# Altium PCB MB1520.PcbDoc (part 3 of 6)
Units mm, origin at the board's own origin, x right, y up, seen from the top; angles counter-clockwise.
Board outline 159 x 88 mm, 6 copper layers (Top Layer, Signal Layer 1, Signal Layer 2, Signal Layer 3, Signal Layer 4, Bottom Layer), stack 1.572 mm thick; 473 components, 377 nets, 1832 pads, 1378 vias.
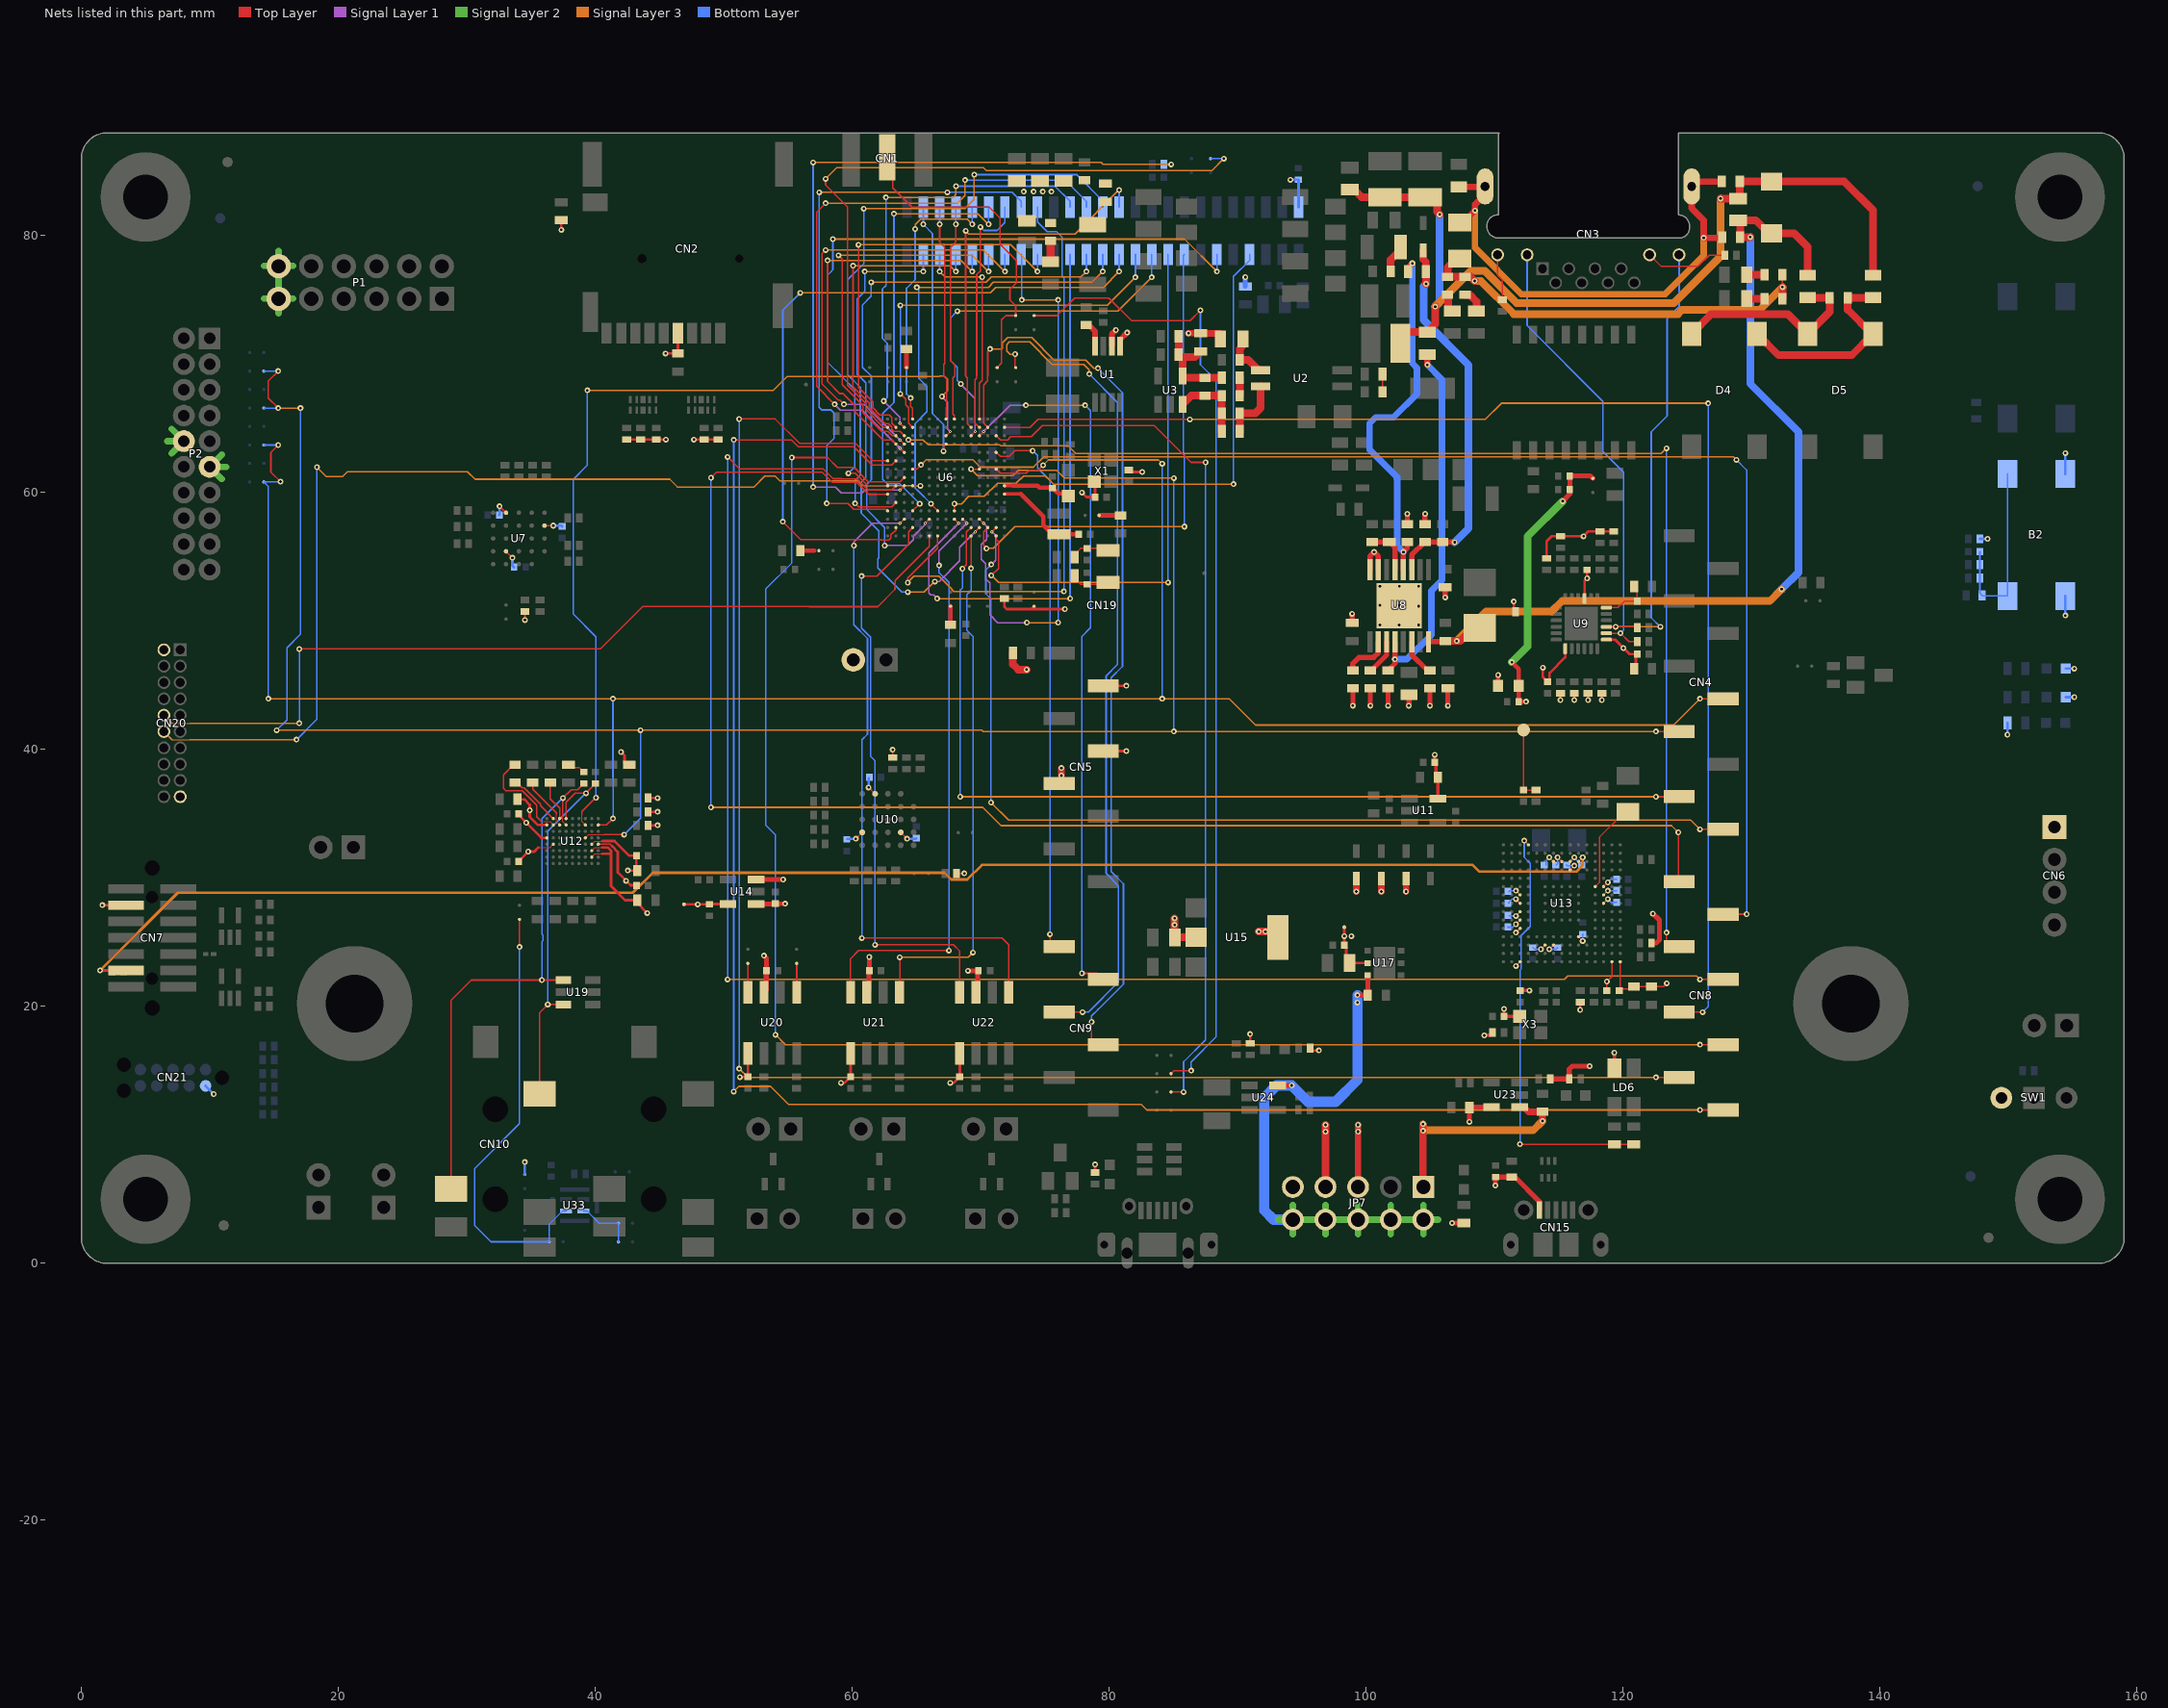
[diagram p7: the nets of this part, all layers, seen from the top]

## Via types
v1: diameter 0.45, hole 0.2, Top Layer to Bottom Layer, tented both sides, 1099 vias
v2: diameter 0.25, hole 0.1, Top Layer to Signal Layer 1, tented both sides, 217 vias
v3: diameter 0.25, hole 0.1, Signal Layer 4 to Bottom Layer, tented both sides, 53 vias
v4: diameter 0.6, hole 0.3, Top Layer to Bottom Layer, tented both sides, 9 vias

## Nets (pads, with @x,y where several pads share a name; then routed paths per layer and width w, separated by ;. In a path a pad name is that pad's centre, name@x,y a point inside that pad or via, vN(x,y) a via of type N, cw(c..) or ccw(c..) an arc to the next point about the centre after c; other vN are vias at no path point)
1V8: C74.2 C82.1 C86.1 C93.2 TP4.1 U12.D1 U12.D8 U12.G9 U14.5 | length 15.6
  Top Layer w0.09: 35.575,32.375 36.475,32.375 U12.D8@36.725,32.625
  Top Layer w0.1: U12.D1@40.225,32.625 41.15,32.625 41.288,32.487
  Top Layer w0.2: C74.2@33.95,36.125 34.475,36.125 34.9,35.7 34.9,34.75 35.525,34.125 U12.G9@36.225,34.125 ; C82.1@34.025,31.3 v1(34.775,32.05) 35.25,32.05 35.575,32.375 ; 41.288,32.487 41.75,32.025 41.75,30.425 42.75,29.425 C86.1@43.2,29.425 ; TP4.1@46.9,27.95 v1(47.975,27.95) C93.2@48.9,27.95 ; C93.2@48.9,27.975 U14.5@50.325,27.975
  other v1: 42.4,29.775 34.9,35.275
3V3: B2.1 B2.2 C24.1 C37.2 C46.1 C77.1 C81.1 C83.2 C87.2 C88.2 C95.1 C96.2 C109.2 C110.2 C111.2 C116.1 C132.2 C136.2 C139.2 C140.2 C141.2 C143.2 CN2.4 CN5.2 CN5.4 CN7.3 CN19.50 CN20.2 CN20.19 CN21.1 JP1.2 L4.2 LD1.1 LD2.1 P1.6 P1.12 R3.2 R27.2 R28.2 R29.2 R30.2 R31.2 R41.2 R49.2 R50.2 R51.1 R55.2 R63.1 R65.2 R67.1 R81.2 R86.1 R90.2 R92.2 R94.1 R102.2 R112.2 R117.2 R118.2 R132.2 R140.2 R145.2 SB22.1 SB36.2 SW1.2 TP5.1 U7.B4 U7.D1 U7.E4 U9.9 U10.B4 U10.D1 U10.E4 U12.B2 U12.C2 U12.D2 U12.E9 U14.1 U14.3 U17.2 U20.5 U21.5 U22.5 X1.4 | length 106.5
  Top Layer w0.09: U12.B2@39.725,31.625 39.975,31.875 40.55,31.875 ; U12.C2@39.725,32.125 39.975,32.375 40.55,32.375 ; U12.D2@39.725,32.625 39.975,32.875 40.55,32.875
  Top Layer w0.127: v1(32.55,58.925) U7.E4@33.05,58.425 ; U7.B4@33.05,55.425 v1(33.55,54.925) ; v1(34.525,50.075) R65.2@34.525,50.75 ; U7.D1@36.05,57.425 v1(36.725,57.425) ; v1(60.275,33.05) U10.E4@60.775,33.55 ; v1(61.275,37.05) U10.D1@61.775,36.55 ; R81.2@63.15,39.375 v1(63.15,39.975) ; U10.B4@63.775,33.55 v1(64.275,33.05) ; R102.2@68.125,30.35 v1(68.725,30.35)
  Top Layer w0.2: v1(1.629,27.879) CN7.3@3.479,27.879 ; C77.1@34.025,34.975 34.025,34.9 35.8,33.125 U12.E9@36.225,33.125 ; v1(37.35,80.45) R3.2@37.35,81.2 ; 40.55,31.875 41.175,31.875 41.225,31.925 ; 40.55,32.375 40.976,32.375 41.225,32.126 41.225,31.925 ; 40.55,32.875 41.5,32.875 42.65,31.725 C81.1@43.2,31.725 43.2,30.65 C83.2@43.275,30.575 v1(42.525,30.575) ; v1(42,39.8) 42.275,39.525 42.275,38.9 42.35,38.825 R86.1@42.65,38.825 ; R27.2@42.45,64.125 R28.2@43.525,64.125 R29.2@44.75,64.125 v1(45.5,64.125) ; v1(44.05,27.275) 43.275,28.05 C88.2@43.275,28.275 42.325,28.275 41.225,29.375 41.225,31.925 ; R94.1@44.1,34.1 v1(44.85,34.1) ; R92.2@44.1,35.15 v1(44.85,35.15) ; R90.2@44.1,36.225 v1(44.85,36.225) ; v1(45.475,70.825) C24.1@46.425,70.825 CN2.4@46.425,72.4 ; v1(47.675,64.125) R30.2@48.475,64.125 R31.2@49.55,64.125 ; v1(51.25,14.5) 51.85,14.5 C109.2@51.87,14.48 ; U20.5@51.87,16.35 51.875,16.345 C109.2@51.875,14.525 ; v1(59.125,14.05) 59.4,14.05 C110.2@59.875,14.525 59.875,16.345 U21.5@59.87,16.35 ; v1(67.625,14.05) 67.9,14.05 C111.2@68.375,14.525 68.375,16.345 U22.5@68.37,16.35 ; R63.1@71.85,51.75 71.85,51.098 72.023,50.925 73.925,50.925 ; SB22.1@74.15,51.15 73.925,50.925 ; v1(76.55,50.925) 73.925,50.925 ; v1(77.875,60) 78.225,59.65 C37.2@78.9,59.65 78.9,60.8 X1.4@78.85,60.85 ; R132.2@78.9,7.075 v1(78.9,7.7) ; CN5.4@79.541,39.88 v1(81.335,39.88) ; CN5.2@79.541,44.96 v1(81.335,44.96) ; R41.2@81.525,61.75 81.675,61.6 v1(82.575,61.6) ; R117.2@90.975,17.125 v1(90.975,17.85) ; R118.2@95.637,16.764 95.826,16.575 v1(96.325,16.575) ; TP5.1@98.325,26.2 TP5.1@98.3,26.175 v1(98.3,25.475) C95.1@98.3,24.775 98.45,24.625 98.45,23.625 C96.2@98.7,23.375 U17.2@100.125,23.375 ; v1(111.498,51.515) 111.498,50.852 R67.1@111.625,50.725 ; R55.2@114.05,54.875 114.05,56.225 114.425,56.6 R51.1@115.125,56.6 v1(116.925,56.6) 117.3,56.975 R49.2@118.2,56.975 R50.2@119.275,56.975 ; v1(116.661,19.731) R112.2@116.661,20.339 ; U9.9@117,51.75 117,53.125 v1(117.2,53.325) C46.1@117.2,53.975
  Top Layer w0.35: U14.1@52.525,27.975 54,27.975 C87.2@54.025,28 v1(54.775,28) ; U14.3@52.525,29.875 v1(54.625,29.875) ; L4.2@110.275,44.95 v1(110.275,45.8)
  Signal Layer 2 w0.5: 14.2,75.11 P1.6@15.35,75.11 ; 14.2,77.65 P1.12@15.35,77.65 ; 15.35,73.96 P1.6@15.35,75.11 ; 15.35,78.8 P1.12@15.35,77.65 ; 16.5,75.11 P1.6@15.35,75.11 ; 16.5,77.65 P1.12@15.35,77.65 ; P1.6@15.35,75.11 P1.12@15.35,77.65
  Bottom Layer w0.127: C143.2@59.575,33 C143.2@59.625,33.05 ; C140.2@61.275,37.775 C140.2@61.325,37.825 ; C141.2@64.95,33.05 C141.2@65,33.1
  Bottom Layer w0.2: CN21.1@9.665,13.815 v1(10.305,13.175) ; C132.2@32.525,58.25 32.55,58.275 v1(32.55,58.925) ; v1(33.55,54.925) 33.55,54.315 C139.2@33.675,54.19 ; SB36.2@34.512,6.919 v1(34.512,7.887) ; v1(36.725,57.425) 37.375,57.425 C136.2@37.425,57.375 ; C143.2@59.625,33.05 v1(60.275,33.05) ; v1(61.275,37.05) C140.2@61.275,37.775 ; v1(64.275,33.05) C141.2@64.95,33.05 ; v1(94.1,84.35) C116.1@94.725,84.35 94.74,84.335 CN19.50@94.74,82.217 ; R140.2@147.775,56.4 v1(148.375,56.4) ; v1(149.925,41.15) R145.2@149.925,42.075 ; v1(154.425,50.425) B2.1@154.425,51.95 ; B2.2@154.425,61.45 v1(154.425,63.075) ; LD1.1@154.45,44.075 v1(155.125,44.075) ; LD2.1@154.45,46.3 v1(155.125,46.3)
  other v1: 98.85,25.475 34.625,34.3
3V3_STLK: C63.2 C70.2 C101.2 C102.2 C103.2 C105.2 C106.2 C108.2 C144.2 C145.2 C146.2 C147.2 C148.2 C149.2 C150.2 C151.2 C152.2 C153.2 C154.2 C155.2 C156.2 C157.2 CN6.1 LD6.4 R115.1 U11.5 U13.C1 U13.C5 U13.C6 U13.C7 U13.C8 U13.C9 U13.F3 U13.G3 U13.G13 U13.H13 U13.J12 U13.J13 U13.K4 U13.N8 U13.N9 U13.N10 U13.P1 U13.R1 X3.4 | length 33.4
  Top Layer w0.12: v1(111.658,23.152) U13.C1@111.983,23.477 ; v1(111.658,25.752) U13.C5@111.983,26.077 ; v1(111.658,26.402) U13.C6@111.983,26.727 ; v1(111.658,27.052) U13.C7@111.983,27.377 ; v1(111.658,28.352) U13.C8@111.983,28.027 ; v1(111.658,29.002) U13.C9@111.983,28.677 ; v1(113.608,24.452) U13.F3@113.933,24.777 ; v1(114.258,24.452) U13.G3@114.583,24.777 ; v1(114.258,31.602) U13.G13@114.583,31.277 ; v1(114.908,31.602) U13.H13@115.233,31.277 ; U13.J12@115.883,30.627 v1(116.208,30.952) ; U13.J13@115.883,31.277 v1(116.208,31.602) ; U13.K4@116.533,25.427 v1(116.858,25.102) ; U13.N8@118.483,28.027 v1(118.808,28.352) ; U13.N9@118.483,28.677 v1(118.808,29.002) ; U13.N10@118.483,29.327 v1(118.808,29.652) ; C105.2@118.736,21.239 v1(118.736,21.936) 119.133,22.333 U13.P1@119.133,23.477 ; C106.2@119.686,21.239 C106.2@119.783,21.336 ; U13.R1@119.783,23.477 C106.2@119.783,21.336 ; v1(123.4,21.8) 123.139,21.539 C102.2@122.211,21.539 C101.2@120.836,21.539 120.647,21.35 119.797,21.35 C106.2@119.783,21.336
  Top Layer w0.254: v1(105.336,39.586) C63.2@105.336,38.989 105.425,38.901 105.425,38.001 C70.2@105.586,37.839 U11.5@105.586,36.189 ; v1(109.2,17.75) 109.622,17.75 R115.1@109.836,17.964 ; v1(110.736,19.811) C108.2@110.736,19.214 X3.4@111.961,19.214 ; C103.2@111.986,21.239 v1(112.711,21.239) ; v1(119.325,16.4) 119.325,15.201 LD6.4@119.336,15.189
  Bottom Layer w0.12: C155.2@111.025,26.175 111.431,26.175 v1(111.658,26.402) ; C152.2@111.111,28.014 111.111,28.111 111.352,28.352 v1(111.658,28.352) ; C150.2@111.111,28.914 111.199,29.002 v1(111.658,29.002) ; C153.2@111.125,27.05 111.127,27.052 v1(111.658,27.052) ; C157.2@112.975,24.575 113.098,24.452 v1(113.608,24.452) ; C147.2@114,31 114,31.344 v1(114.258,31.602) ; v1(114.258,24.452) 114.777,24.452 C156.2@114.9,24.575 ; C146.2@114.8,31 114.908,31.108 v1(114.908,31.602) ; C145.2@115.6,31 115.648,30.952 v1(116.208,30.952) ; v1(116.208,31.602) 116.208,31.592 C144.2@116.8,31 ; v1(116.858,25.102) 116.858,25.608 C154.2@116.875,25.625 ; v1(118.808,28.352) 119.06,28.1 C151.2@119.5,28.1 ; v1(118.808,29.002) 119.498,29.002 C149.2@119.5,29 ; v1(118.808,29.652) 119.056,29.9 C148.2@119.5,29.9
5V: C98.2 C99.2 C100.2 C107.2 CN5.5 JP7.2 JP7.4 JP7.6 JP7.8 JP7.10 P2.6 P2.15 R107.1 R134.1 R138.1 U1.1 U1.2 U17.3 U20.3 U21.3 U22.3 U24.5 | length 79.1
  Top Layer w0.381: v1(53.125,23.95) 53.325,23.75 C98.2@53.325,22.775 53.3,22.75 53.3,21.26 U20.3@53.14,21.1 ; U21.3@61.14,21.1 61.3,21.26 61.3,22.75 C99.2@61.325,22.775 v1(61.325,23.85) ; v1(69,22.775) C100.2@69.825,22.775 69.775,22.725 69.775,21.235 U22.3@69.64,21.1 ; CN5.5@76.112,37.34 CN5.5@76.3,37.529 ; U24.5@93.125,13.85 v1(94.2,13.85) ; v1(99.32,20.875) C107.2@100.125,20.875 U17.3@100.125,22.425 ; v1(106.686,3.139) R134.1@107.611,3.139 ; R107.1@122.211,24.939 122.589,24.939 122.825,25.175 122.825,26.725 v1(122.325,27.225)
  Top Layer w0.45: U1.2@80.2,71.4 80.2,72.325 v1(80.525,72.65) ; U1.1@80.85,71.4 80.85,71.9 v1(81.4,72.45)
  Top Layer w0.5: v1(76.275,38.552) 76.275,37.554 CN5.5@76.3,37.529
  Signal Layer 2 w0.5: 6.675,64 P2.15@7.975,64 ; 7.025,63.05 P2.15@7.975,64 ; 7.025,64.95 P2.15@7.975,64 ; 10.925,61.05 P2.6@9.975,62 ; 10.925,62.95 P2.6@9.975,62 ; 11.275,62 P2.6@9.975,62 ; 93.145,3.405 JP7.10@94.295,3.405 ; 94.295,2.255 JP7.10@94.295,3.405 ; 94.295,4.555 JP7.10@94.295,3.405 ; 96.835,2.255 JP7.8@96.835,3.405 ; 96.835,4.555 JP7.8@96.835,3.405 ; 99.375,2.255 JP7.6@99.375,3.405 ; 99.375,4.555 JP7.6@99.375,3.405 ; 101.915,2.255 JP7.4@101.915,3.405 ; 101.915,4.555 JP7.4@101.915,3.405 ; 104.455,2.255 JP7.2@104.455,3.405 ; 104.455,4.555 JP7.2@104.455,3.405 ; 105.605,3.405 JP7.2@104.455,3.405 ; JP7.10@94.295,3.405 JP7.8@96.835,3.405 ; JP7.8@96.835,3.405 JP7.6@99.375,3.405 ; JP7.6@99.375,3.405 JP7.4@101.915,3.405 ; JP7.4@101.915,3.405 JP7.2@104.455,3.405
  Bottom Layer w0.381: R138.1@90.6,76.05 v1(90.6,76.775)
  Bottom Layer w0.8: JP7.10@94.295,3.405 92.795,3.405 92.075,4.125 92.075,12.9 93.025,13.85 v1(94.2,13.85) 95.475,12.575 97.625,12.575 99.32,14.27 v1(99.32,20.875)
  other v1: 99.32,20.3 76.275,37.975
5V_POE: C3.2 C4.2 C5.2 C6.2 D10.1 JP7.5 R2.2 R18.2 R20.2 | length 8.8
  Top Layer w0.508: v1(86.175,72.4) 87.101,72.4 R20.2@87.111,72.389 88.661,72.389 R18.2@88.661,71.964 ; JP7.5@99.375,5.945 v1(99.375,10.778) ; v1(103.111,28.939) D10.1@103.111,29.944
  other v1: 99.375,10.25 73.35,83.425 74.125,83.425 74.825,83.425 75.5,83.425
5V_USB_CHGR: C114.2 C115.2 CN15.1 D8.1 JP7.9 R125.2 R126.2 U23.5 U30.1 | length 13.3
  Top Layer w0.4: v1(108.036,11.011) C114.2@108.036,12.139 108.061,12.164 U23.5@109.761,12.164 ; v1(110.061,6.061) C115.2@110.061,6.714 U30.1@111.336,6.714 111.586,6.714 113.475,4.826 CN15.1@113.475,4.15 ; R125.2@114.336,14.364 R126.2@115.811,14.364 115.811,15.111 116.05,15.35 v1(117.4,15.35)
  Top Layer w0.508: v1(99.236,28.939) D8.1@99.236,29.944
5V_USB_STLK: C113.2 JP7.1 U23.1 | length 17.7
  Top Layer w0.508: U23.1@111.961,12.164 112.286,12.164 112.65,11.8 C113.2@113.725,11.8 v1(113.725,11.075)
  Top Layer w0.55: v1(104.425,10.843) v1(104.425,10.315) 104.425,6.1 JP7.1@104.58,5.945
  Signal Layer 3 w0.55: v1(104.425,10.315) v1(104.425,10.843)
  Signal Layer 3 w0.6: v1@104.455,10.35 113,10.35 v1(113.725,11.075)
ADC_IN: CN1.1 SB4.1 SB41.2 | length 25.5
  Top Layer w0.127: CN1.1@62.725,86.1 62.725,84.8 63.15,84.375 63.15,83.715 64.648,82.217 70.658,82.217 71.499,81.376 71.499,79.326 72.775,78.05 72.775,76.325 72.275,75.825 72.275,75 72.725,74.55 SB41.2@72.725,73.775 71.95,73.775 71.625,73.45 71.625,70.075 SB4.1@71.275,69.725
AGND: C40.1 C41.1 C57.2 C58.2 R61.2 R69.2 U8.15 U8.16 | length 8.8
  Top Layer w0.381: R69.2@98.918,49.846 v1(98.918,50.568) ; v1(98.961,43.414) C57.2@98.961,44.764 ; v1(100.336,43.414) C58.2@100.336,44.764
  Top Layer w0.4: U8.16@100.301,53.996 100.301,55.051 v1(100.625,55.375) 100.951,55.049 U8.15@100.951,53.996 ; C40.1@103.211,57.539 v1(103.211,58.336) ; C41.1@104.586,57.539 v1(104.586,58.336) ; v1(106.157,51.84) R61.2@106.157,52.637
ARD_A0: CN9.1 U6.L2 | length 43.1
  Top Layer w0.1: U6.L2@71.2,63.125 71.525,62.8 72.225,62.8 72.675,63.25 v1(74.05,63.25)
  Top Layer w0.12: v1(75.395,25.62) 75.395,24.64 CN9.1@76.112,24.64
  Bottom Layer w0.1: v1(74.05,63.25) 74.425,62.875 74.425,61.925 75.395,60.955 75.395,52.625
  Bottom Layer w0.12: v1(75.395,25.62) 75.395,52.625
ARD_A1: CN9.2 U6.N4 | length 55.8
  Top Layer w0.12: v1(77.875,22.575) 79.066,22.575 CN9.2@79.541,22.1
  Top Layer w0.127: U6.N4@69.9,64.425 v2(70.225,64.75)
  Signal Layer 1 w0.1: v2(70.225,64.75) 72.275,66.8 v1(73.525,66.8)
  Signal Layer 3 w0.1: v1(73.525,66.8) 75.425,66.8
  Signal Layer 3 w0.12: 75.425,66.8 v1(78.125,66.8)
  Bottom Layer w0.12: v1(77.875,22.575) 77.875,48.8 78.555,49.48 78.555,66.37 v1(78.125,66.8)
ARD_A2: CN9.3 SB5.1 | length 64.7
  Top Layer w0.12: CN9.3@76.112,19.56 v1(77.928,19.56)
  Top Layer w0.13: v1(72.675,70.775) 72.675,69.775 SB5.1@72.725,69.725
  Signal Layer 3 w0.104: v1(72.675,70.775) 72.275,70.775 72.025,71.025 72.025,71.525 72.225,71.725 73.825,71.725 75.563,69.987 78.038,69.987 78.45,69.575 v1(78.45,69.225)
  Bottom Layer w0.13: v1(77.928,19.56) 78.387,19.56 80.725,21.898 80.725,29.386 79.769,30.342 79.769,45.744 80.65,46.625 80.65,67.025 v1(78.45,69.225)
ARD_A3: CN9.4 U6.P3 | length 72.6
  Top Layer w0.1: 70.542,69.083 70.542,68.692 70.225,68.375 70.225,65.4 U6.P3@70.55,65.075
  Top Layer w0.13: 70.542,69.083 70.542,70.992 v1(70.725,71.175) ; v1(78.625,18.8) 78.625,17.02 CN9.4@79.541,17.02
  Signal Layer 3 w0.104: v1(70.725,71.175) 71.625,71.175 71.694,71.244 71.694,71.662 72.088,72.056 73.962,72.056 75.7,70.318 78.175,70.318 78.818,69.675 v1(79.125,69.675)
  Bottom Layer w0.13: v1(78.625,18.8) 78.625,19.259 79.125,19.759 81.106,21.74 81.106,29.544 80.15,30.5 80.15,45.586 81.031,46.467 81.031,67.769 v1(79.125,69.675)
ARD_A4: SB32.1 SB42.2 | length 76.8
  Top Layer w0.12: SB42.2@74.15,73.775 75.925,73.775 77.3,75.15 79.975,75.15 81.75,73.375 86.29,73.375 v1(87.1,74.185) ; SB32.1@84.811,14.764 85.047,15 v1(86.375,15)
  Bottom Layer w0.12: v1(86.375,15) 86.375,15.675 88.325,17.625 88.325,68.725 87.1,69.95 v1(87.1,74.185)
ARD_A5: SB33.1 U6.N2 | length 68.8
  Top Layer w0.1: U6.N2@71.2,64.425 71.525,64.1 72.092,64.1 72.342,64.35 73.949,64.35 74.812,65.213 75.438,65.213
  Top Layer w0.12: 75.438,65.213 83.515,65.213 86.378,62.35 v1(87.5,62.35) ; SB33.1@84.811,13.339 v1(85.789,13.339)
  Bottom Layer w0.12: v1(85.789,13.339) 85.789,15.689 87.5,17.4 v1(87.5,62.35)
ARD_D0: CN8.1 U6.K14 | length 142.2
  Top Layer w0.12: v1(50.775,64.1) 55.275,64.1 55.8,63.575 60.125,63.575 61.55,62.15 63.075,62.15 U6.K14@63.4,62.475 ; v1(125.984,11.94) CN8.1@127.801,11.94
  Signal Layer 3 w0.12: v1(50.775,13.375) 51.175,13.775 53.65,13.775 55.05,12.375 82.5,12.375 82.935,11.94 v1(125.984,11.94)
  Bottom Layer w0.12: v1(50.775,13.375) v1(50.775,64.1)
ARD_D1: CN8.2 U6.K15 | length 136.9
  Top Layer w0.12: v1(51.2,65.725) 54,65.725 55.9,63.825 59.175,63.825 60.25,63.825 61.6,62.475 U6.K15@62.75,62.475 ; v1(122.555,14.48) CN8.2@124.372,14.48
  Signal Layer 3 w0.12: v1(51.2,15.15) 51.87,14.48 v1(122.555,14.48)
  Bottom Layer w0.12: v1(51.2,15.15) v1(51.2,65.725)
ARD_D2: CN8.3 U6.H13 | length 129.9
  Top Layer w0.1: 59.175,61.95 60.15,61.95 61.25,60.85 63.725,60.85 U6.H13@64.05,61.175
  Top Layer w0.12: v1(125.984,17.02) CN8.3@127.801,17.02
  Top Layer w0.127: v1(55.3,62.725) 58.076,62.725 58.851,61.95 59.175,61.95
  Signal Layer 3 w0.12: v1(54.025,17.8) 54.805,17.02 v1(125.984,17.02)
  Bottom Layer w0.12: v1(54.025,17.8) 54.025,33.351 53.252,34.125 53.252,52.476 55.3,54.525 v1(55.3,62.725)
ARD_D3: CN8.4 U6.P1 | length 104.9
  Top Layer w0.1: U6.P1@71.85,65.075 73.825,65.075 74.45,65.7 75.425,65.7
  Top Layer w0.12: CN8.4@124.372,19.56 v1(126.188,19.56)
  Top Layer w0.127: 75.425,65.7 v1(86.275,65.7)
  Signal Layer 3 w0.127: v1(86.275,65.7) 109.275,65.7 110.525,66.95 v1(126.625,66.95)
  Bottom Layer w0.12: v1(126.188,19.56) 126.625,19.997 v1(126.625,66.95)
ARD_D4: CN8.5 U6.G14 | length 132.7
  Top Layer w0.1: 59.175,61.075 60.367,61.075 61.242,60.2 63.075,60.2 U6.G14@63.4,60.525
  Top Layer w0.12: v1(50.3,62.775) 51.225,61.85 54.025,61.85 ; v1(125.984,22.1) CN8.5@127.801,22.1
  Top Layer w0.127: 54.025,61.85 57.743,61.85 58.518,61.075 59.175,61.075
  Signal Layer 3 w0.12: v1(50.3,22.1) 115.425,22.1 115.7,22.375 125.71,22.375 v1(125.984,22.1)
  Bottom Layer w0.12: v1(50.3,22.1) v1(50.3,62.775)
ARD_D5: CN8.6 U6.M12 | length 99.9
  Top Layer w0.12: v1(123.375,25.75) 123.375,24.64 CN8.6@124.372,24.64
  Top Layer w0.127: v1(64.375,64.1) U6.M12@64.7,63.775
  Signal Layer 3 w0.1: v1(64.375,64.1) 65.53,64.1 65.925,63.705 71.495,63.705 71.555,63.645 75.425,63.645
  Signal Layer 3 w0.12: 75.425,63.645 76.805,63.645 77.405,63.045 122.97,63.045 v1(123.375,63.45)
  Bottom Layer w0.12: v1(123.375,25.75) v1(123.375,63.45)
ARD_D6: CN8.7 U6.J12 | length 102.6
  Top Layer w0.12: CN8.7@127.8,27.18 v1(129.617,27.18)
  Top Layer w0.127: U6.J12@64.7,61.825 65.025,61.825 v1(65.35,62.15)
  Signal Layer 3 w0.127: v1(65.35,62.15) 65.758,62.559 69.391,62.559 69.975,61.975 74.1,61.975 74.905,62.78 128.595,62.78 v1(128.825,62.55)
  Bottom Layer w0.12: v1(128.825,62.55) 129.617,61.758 v1(129.617,27.18)
ARD_D7: CN8.8 U6.F15 | length 120.2
  Top Layer w0.1: 59.175,60.812 60.347,60.812 61.284,59.875 U6.F15@62.75,59.875
  Top Layer w0.12: v1(124.3,33.55) 124.3,29.793 CN8.8@124.372,29.72
  Top Layer w0.127: v1(49,61.15) 49.425,61.575 57.669,61.575 58.431,60.812 59.175,60.812
  Signal Layer 3 w0.12: v1(49,35.5) 70.15,35.5 71.575,34.075 123.775,34.075 v1(124.3,33.55)
  Bottom Layer w0.127: v1(49,35.5) v1(49,61.15)
ARD_D8: CN4.1 U6.B2 | length 80
  Top Layer w0.12: v1(125.984,33.784) CN4.1@127.801,33.784
  Top Layer w0.127: v2(70.875,56.95) U6.B2@71.2,57.275
  Signal Layer 1 w0.1: v1(70.825,54.4) 71.15,54.725 71.15,56.675 v2(70.875,56.95)
  Signal Layer 3 w0.12: v1(70.8,35.875) 72.175,34.5 125.269,34.5 v1(125.984,33.784)
  Bottom Layer w0.12: v1(70.8,35.875) 70.8,51.725 70.4,52.125 70.4,53.975 v1(70.825,54.4)
ARD_D9: CN4.2 U6.B5 | length 77.3
  Top Layer w0.1: v1(68.575,54.075) 68.9,54.4 68.9,56.925 U6.B5@69.25,57.275
  Top Layer w0.12: v1(122.555,36.324) CN4.2@124.372,36.324
  Signal Layer 3 w0.12: v1@68.376,36.324 v1(122.555,36.324) ; v1@68.376,36.325 v1(68.4,36.325)
  Bottom Layer w0.1: 68.575,52.625 v1(68.575,54.075)
  Bottom Layer w0.12: v1(68.4,36.325) 68.4,52.4 68.575,52.575 68.575,52.625
ARD_D11: CN4.4 SB12.1 SB15.1 U6.J4 U12.E3 | length 191.1
  Top Layer w0.09: U12.E3@39.225,33.125 39.475,33.375 40.675,33.375
  Top Layer w0.1: 40.675,33.375 v1(42.25,33.375) ; v1(69.25,61.825) U6.J4@69.9,61.825
  Top Layer w0.12: v1(15.325,66.575) 14.55,67.35 14.55,68.675 v1(15.325,69.45) ; v1(122.555,41.404) CN4.4@124.372,41.404
  Signal Layer 3 w0.1: v1(69.25,61.825) 69.757,61.318 72.518,61.318 72.925,61.725 75.402,61.725 75.407,61.72 75.425,61.72
  Signal Layer 3 w0.12: v1(15.2,41.5) v1(43.525,41.5) 70.1,41.5 70.196,41.404 v1(85.025,41.404) v1(122.555,41.404) ; v1(15.325,66.575) v1(17.05,66.575) ; 75.425,61.72 75.93,61.72 76.525,61.125 v1(85.025,61.125)
  Bottom Layer w0.1: v1(42.25,33.375) 43.525,34.65 43.525,37.8
  Bottom Layer w0.12: SB12.1@14.2,66.575 v1(15.325,66.575) ; SB15.1@14.2,69.45 v1(15.325,69.45) ; v1(15.2,41.5) 15.995,42.295 15.995,47.92 17.05,48.975 v1(17.05,66.575) ; 43.525,37.8 v1(43.525,41.5) ; v1(85.025,41.404) v1(85.025,61.125)
ARD_D12: CN4.5 SB6.1 SB8.1 U6.J2 U12.G1 | length 180.2
  Top Layer w0.1: U12.G1@40.225,34.125 40.875,34.125 v1(41.375,34.625) ; U6.J2@71.2,61.825 71.525,61.5 73.525,61.5 73.775,61.75 74.475,61.75 v1(74.85,62.125)
  Top Layer w0.12: v1(15.325,63.7) 14.75,63.125 14.75,61.589 v1(15.491,60.847) ; v1(125.984,43.944) CN4.5@127.801,43.944
  Signal Layer 3 w0.12: v1(14.55,43.944) v1(41.375,43.944) v1(84.125,43.944) 89.356,43.944 91.4,41.9 123.94,41.9 v1(125.984,43.944) ; v1(74.85,62.125) 75.261,62.536 83.839,62.536 v1(84.125,62.25)
  Bottom Layer w0.1: v1(41.375,34.625) 41.375,37.8
  Bottom Layer w0.12: SB6.1@14.2,60.825 14.55,60.475 v1(14.55,43.944) ; SB8.1@14.2,63.7 v1(15.325,63.7) ; 14.366,60.847 v1(15.491,60.847) ; 41.375,37.8 v1(41.375,43.944) ; v1(84.125,43.944) v1(84.125,62.25)
Audio_Int: U6.N8 U12.G3 | length 69.2
  Top Layer w0.09: 38.975,34.95 38.975,34.375 U12.G3@39.225,34.125
  Top Layer w0.1: 38.975,34.95 38.975,35.175 v1(40.05,36.25)
  Top Layer w0.127: U6.N8@67.3,64.425 v2(67.625,64.75)
  Signal Layer 1 w0.1: v1(66.975,67.475) 67.425,67.025 67.425,64.95 v2(67.625,64.75)
  Signal Layer 3 w0.12: v1(39.375,67.95) 53.85,67.95 54.925,69.025 66.75,69.025 66.805,69.08 67.143,69.08 67.273,68.95 67.275,68.95 67.425,68.8 67.425,67.925 v1(66.975,67.475)
  Bottom Layer w0.1: v1(40.05,36.25) 40.05,37.8
  Bottom Layer w0.12: v1(39.375,67.95) 39.375,62.125 38.276,61.026 38.276,50.55 40.05,48.776 40.05,37.8
Chassis: C8.1 C10.1 C13.2 CN3.SH1 CN3.SH2 R1.1 | length 39
  Top Layer w0.5: R1.1@107.211,83.789 109.224,83.789 CN3.SH1@109.26,83.825 109.26,83.21 108.475,82.425 v1(108.475,81.953) 107.536,81.014 C10.1@107.286,81.014 ; C8.1@127.686,84.214 125.729,84.214 CN3.SH2@125.34,83.825 125.34,82.135 126.275,81.2 v1(126.275,79.825) 127.647,79.825 C13.2@127.711,79.889
  Signal Layer 3 w0.5: v1(108.475,81.953) 108.475,79.04 112.065,75.45 123.275,75.45 126.275,78.45 v1(126.275,79.825)
CTP_INT: CN19.39 U6.G15 | length 55.2
  Top Layer w0.1: v1(59.7,61.502) 60.223,61.502 61.2,60.525 U6.G15@62.75,60.525
  Signal Layer 3 w0.12: v1(58.488,79.725) 85.865,79.725 v1(88.39,77.2)
  Bottom Layer w0.1: 59.175,69.046 59.2,69.021
  Bottom Layer w0.12: 58.336,77.187 58.079,76.93 58.079,70.142 59.175,69.046
  Bottom Layer w0.127: 58.336,77.187 58.488,77.339 v1(58.488,79.725) ; 59.2,69.021 60.2,68.021 60.2,62.002 v1(59.7,61.502) ; v1(88.39,77.2) CN19.39@88.39,78.531
DETECTn: CN20.10 U6.A10 | length 70.1
  Top Layer w0.1: 63.325,52.625 63.325,53.15 66,55.825 U6.A10@66,56.625
  Top Layer w0.12: v1(16.962,47.825) 40.375,47.825 43.669,51.119 56.625,51.119
  Top Layer w0.127: 56.625,51.119 61.981,51.119 63.325,52.463 63.325,52.625
  Signal Layer 3 w0.09: 7.06,42.037 8.45,42.037
  Signal Layer 3 w0.12: 8.45,42.037 v1(16.962,42.037)
  Signal Layer 3 w0.127: CN20.10@6.425,42.672 7.06,42.037
  Bottom Layer w0.12: v1(16.962,42.037) v1(16.962,47.825)
E5V: C94.2 D9.1 JP7.7 R72.1 U15.2 U15.4 | length 12.8
  Top Layer w0.508: v1(101.186,28.939) D9.1@101.186,29.944
  Top Layer w0.6: R72.1@72.511,47.514 72.511,46.639 72.925,46.225 v1(73.575,46.225) ; v1(85.096,26.864) 85.096,25.379 C94.2@85.1,25.375 U15.2@86.775,25.375 ; v1(91.65,25.825) 92.675,25.825 U15.4@93.125,25.375 ; JP7.7@96.835,5.945 v1(96.835,10.778)
  other v1: 96.835,10.25 92.163,25.825 85.096,26.35
FDCAN1_RX: U6.B12 U22.4 | length 45.3
  Top Layer w0.1: v1(60.725,53.5) 61.917,53.5 64.375,55.958 64.375,56.95 U6.B12@64.7,57.275
  Top Layer w0.12: v1(61.775,24.8) 67.875,24.8 68.37,24.305 U22.4@68.37,21.1
  Bottom Layer w0.12: v1(60.725,53.5) 60.725,49.439 61.425,48.739 61.425,39.475 61.775,39.125 v1(61.775,24.8)
FDCAN1_TX: U6.C13 U22.1 | length 51.4
  Top Layer w0.12: v1(60.75,25.325) 71.65,25.325 72.18,24.795 U22.1@72.18,21.1
  Top Layer w0.127: v2(63.725,57.6) U6.C13@64.05,57.925
  Signal Layer 1 w0.1: v1(60.125,55.875) 60.125,56.15 61.575,57.6 v2(63.725,57.6)
  Bottom Layer w0.12: v1(60.125,55.875) 60.125,49.7 61.185,48.64 61.185,41.185 60.75,40.75 v1(60.75,25.325)
FDCAN2_RX: U6.C6 U21.4 | length 45.5
  Top Layer w0.12: U21.4@59.87,21.1 59.87,23.72 60.5,24.35 v1(67.525,24.35)
  Top Layer w0.127: U6.C6@68.6,57.925 v2(68.925,57.6)
  Signal Layer 1 w0.1: v1(66.75,54.325) 66.75,55.425 v2(68.925,57.6)
  Bottom Layer w0.12: v1(66.75,54.325) 66.75,53.775 67.525,53 v1(67.525,24.35)
FDCAN2_TX: U6.A5 U21.1 | length 41.3
  Top Layer w0.1: v1(69.25,54.1) U6.A5@69.25,56.625
  Top Layer w0.12: U21.1@63.68,21.1 63.7,21.12 v1(63.7,23.825)
  Signal Layer 3 w0.12: v1(63.7,23.825) 69.025,23.825 v1(69.405,24.205)
  Bottom Layer w0.1: 69.25,52.625 v1(69.25,54.1)
  Bottom Layer w0.12: 69.25,52.625 69.25,52.375 68.925,52.05 68.925,49.275 69.405,48.795 v1(69.405,24.205)
FDCAN3_RX: SB29.1 U20.4 | length 2.3
  Top Layer w0.12: U20.4@51.87,21.1 51.87,23.345 SB29.1@51.875,23.35
FDCAN3_TX: SB30.1 U20.1 | length 2.3
  Top Layer w0.12: SB30.1@55.675,23.35 55.68,23.345 U20.1@55.68,21.1
GNDDetect: CN7.11 R146.2 U13.K13 | length 123.7
  Top Layer w0.12: U13.K13@116.533,31.277 v1(116.858,31.602)
  Top Layer w0.2: v1(1.45,22.8) CN7.11@3.479,22.799
  Signal Layer 3 w0.2: v1(1.45,22.8) 7.5,28.85 42.925,28.85 44.475,30.4 67.175,30.4 67.7,29.875 68.95,29.875 70.089,31.014 108.286,31.014 108.793,30.507 112.492,30.507 116.392,30.507 116.858,30.972 v1(116.858,31.602)
  Bottom Layer w0.2: v1(1.45,22.8) 2.376,22.8 R146.2@2.386,22.789
LCD_B0: CN19.21 U6.C7 | length 44.8
  Top Layer w0.127: U6.C7@67.95,57.925 v2(68.275,57.6)
  Signal Layer 1 w0.1: v1(66.6,51.75) 66.32,52.03 66.12,52.03 65.978,52.172 65.978,55.303 v2(68.275,57.6)
  Signal Layer 3 w0.102: v1(66.6,51.75) v1(76.96,51.75)
  Bottom Layer w0.127: v1(76.96,51.75) CN19.21@76.96,78.531
LCD_B1: CN19.23 U6.C10 | length 44.7
  Top Layer w0.127: v2(65.675,57.6) U6.C10@66,57.925
  Signal Layer 1 w0.1: v1(62.525,55.875) 64.3,55.875 64.778,56.353 64.778,56.619 65.675,57.516 v2(65.675,57.6)
  Signal Layer 3 w0.102: v1(61.477,76.373) 70.423,76.373 70.825,76.775 77.805,76.775 v1(78.23,77.2)
  Bottom Layer w0.127: v1(61.477,76.373) 61.477,75.277 60.802,74.602 60.802,69.748 61.481,69.069 61.481,61.006 61.121,60.646 61.121,58.682 62.525,57.279 v1(62.525,55.875) ; v1(78.23,77.2) CN19.23@78.23,78.531
LCD_B2: CN19.25 U6.D9 | length 35.2
  Top Layer w0.127: v1(66.125,59.125) 66.125,59.1 U6.D9@66.65,58.575
  Signal Layer 3 w0.102: v1@65,75.971 v1(65.025,75.971) 70.59,75.971 70.992,76.373 78.673,76.373 v1(79.5,77.2)
  Bottom Layer w0.127: v1(65.025,75.971) 65.166,75.83 65.166,68.909 65.82,68.255 65.82,66.295 64.891,65.366 64.891,60.356 65.131,60.116 65.134,60.116 v1(66.125,59.125) ; v1(79.5,77.2) CN19.25@79.5,78.531
LCD_B3: CN19.27 U6.B14 | length 55.3
  Top Layer w0.1: 59.002,56.35 62.2,56.35 62.25,56.3 62.87,56.3 63.02,56.45 63.02,56.72 63.4,57.1 U6.B14@63.4,57.275
  Top Layer w0.127: v1(54.6,57.725) 55.975,56.35 59.002,56.35
  Signal Layer 3 w0.102: v1(55.95,75.55) 70.737,75.55 71.158,75.971 79.541,75.971 v1(80.77,77.2)
  Bottom Layer w0.127: v1(54.6,57.725) 54.6,74.2 v1(55.95,75.55) ; v1(80.77,77.2) CN19.27@80.77,78.531
LCD_B4: CN19.29 U6.P12 | length 30.9
  Top Layer w0.1: v1(63.75,67.675) 64.155,67.27 64.155,66.807 64.375,66.587 64.375,65.4 U6.P12@64.7,65.075
  Signal Layer 3 w0.102: v1(63.75,74.575) 79.855,74.575 v1(82.04,76.76)
  Bottom Layer w0.127: v1(63.75,67.675) v1(63.75,74.575) ; v1(82.04,76.76) CN19.29@82.04,78.531
LCD_B5: CN19.31 U6.N5 | length 28.9
  Top Layer w0.127: U6.N5@69.25,64.425 v2(69.575,64.75)
  Signal Layer 1 w0.1: v1(68.45,68.45) 69.575,67.325 v2(69.575,64.75)
  Signal Layer 3 w0.102: v1(68.175,74.125) 80.675,74.125 v1(83.31,76.76)
  Bottom Layer w0.127: v1(68.175,74.125) 67.636,73.586 67.636,70.289 68.175,69.75 68.175,68.725 v1(68.45,68.45) ; v1(83.31,76.76) CN19.31@83.31,78.531
LCD_B6: CN19.33 U6.A2 | length 42.9
  Top Layer w0.1: v1(70.825,53.55) 71.375,54.1 71.375,56.175 71.2,56.35 U6.A2@71.2,56.625
  Signal Layer 3 w0.1: v1(70.825,53.55) 71.375,53 75.425,53
  Signal Layer 3 w0.102: 75.425,53 v1(84.58,53)
  Bottom Layer w0.127: v1(84.58,53) CN19.33@84.58,78.531
LCD_B7: CN19.35 U6.B3 | length 39.2
  Top Layer w0.1: v1(70.45,55.65) 70.225,55.875 70.225,56.95 U6.B3@70.55,57.275
  Signal Layer 3 w0.1: v1(70.45,55.65) 70.967,55.65 72.667,57.35 75.425,57.35
  Signal Layer 3 w0.102: 75.425,57.35 v1(85.85,57.35)
  Bottom Layer w0.127: v1(85.85,57.35) 85.853,57.353 85.853,63.022 85.766,63.109 85.766,78.448 CN19.35@85.85,78.531
LCD_BL_CTRL: CN19.43 U6.D7 | length 41.8
  Top Layer w0.127: U6.D7@67.95,58.575 v1(67.95,59.125)
  Signal Layer 3 w0.1: v1(67.95,59.125) 68.5,59.125 69.075,59.7 70.284,59.7 71.309,60.725 72.75,60.725 73.325,61.3 75.025,61.3 75.425,60.9
  Signal Layer 3 w0.12: 75.425,60.9 75.675,60.65 v1(89.675,60.65)
  Bottom Layer w0.127: v1(89.675,60.65) 89.675,76.825 90.93,78.08 CN19.43@90.93,78.531
LCD_CLK: R136.2 U6.G13 | length 61.3
  Top Layer w0.127: v2(63.725,60.2) U6.G13@64.05,60.525
  Signal Layer 1 w0.1: v1(56.95,60.425) 58.679,60.425 59.129,59.975 60.75,59.975 60.975,60.2 v2(63.725,60.2)
  Signal Layer 3 w0.102: v1(56.95,85.7) 79.375,85.7 79.525,85.55 v1(84.825,85.55)
  Bottom Layer w0.127: v1(56.95,60.425) v1(56.95,85.7) ; R136.2@84.25,85.55 v1(84.825,85.55)
LCD_DE: CN19.22 U6.P13 | length 35
  Top Layer w0.127: v2(63.725,65.4) U6.P13@64.05,65.075
  Signal Layer 1 w0.1: v1(62.45,67.125) 63.725,65.85 v2(63.725,65.4)
  Signal Layer 3 w0.102: v1(62.625,82.973) 67.873,82.973 68.075,83.175 v1(68.075,83.85)
  Bottom Layer w0.127: v1(62.45,67.125) 62.725,67.4 62.725,71.625 62.35,72 62.35,75.85 62.625,76.125 v1(62.625,82.973) ; v1(68.075,83.85) 75.775,83.85 76.96,82.665 CN19.22@76.96,82.217
LCD_DISP: CN19.24 U6.L13 | length 46.4
  Top Layer w0.127: v1(57.925,82.525) 57.225,81.825 57.225,68.275 v1(58.625,66.875) ; v2(63.725,63.45) U6.L13@64.05,63.125
  Signal Layer 1 w0.1: v1(58.625,66.875) 59.075,66.425 60.75,66.425 v2(63.725,63.45)
  Signal Layer 3 w0.102: v1(57.925,82.525) 68.175,82.525 68.775,83.125 v1(68.775,84.325)
  Bottom Layer w0.127: v1(68.775,84.325) 76.575,84.325 78.23,82.67 CN19.24@78.23,82.217
LCD_G0: CN19.4 U6.M8 | length 20.3
  Top Layer w0.127: v1(67.1,63.225) 67.1,63.575 U6.M8@67.3,63.775
  Bottom Layer w0.127: CN19.4@65.53,82.217 v1(65.53,80.886) 66.246,80.169 66.246,66.154 67.1,65.3 v1(67.1,63.225)
LCD_G1: CN19.6 U6.R8 | length 16.8
  Top Layer w0.1: 67.125,69.075 67.35,68.85 67.35,66.65 67.3,66.6 U6.R8@67.3,65.725
  Top Layer w0.127: v1(66.8,80.886) 66.8,79.5 67.209,79.091 67.209,70.059 67.125,69.975 67.125,69.075
  Bottom Layer w0.127: v1(66.8,80.886) CN19.6@66.8,82.217
LCD_G2: CN19.8 U6.R7 | length 16.9
  Top Layer w0.1: U6.R7@67.95,65.725 67.95,66 67.825,66.125 67.825,68.921 67.979,69.075
  Top Layer w0.127: 67.979,69.075 67.979,69.946 67.636,70.289 67.636,79.069 68.07,79.503 v1(68.07,80.886)
  Bottom Layer w0.127: v1(68.07,80.886) CN19.8@68.07,82.217
LCD_G3: CN19.10 U6.R12 | length 21.7
  Top Layer w0.1: v1(64.55,67.35) 64.55,66.695 64.7,66.545 U6.R12@64.7,65.725
  Signal Layer 3 w0.102: v1(64.895,80.52) 64.895,80.87 65.307,81.282 68.944,81.282 v1(69.34,80.886)
  Bottom Layer w0.127: v1(64.55,67.35) 64.225,67.675 64.225,75.9 64.895,76.57 v1(64.895,80.52) ; v1(69.34,80.886) CN19.10@69.34,82.217
LCD_G4: CN19.12 U6.D12 | length 34.5
  Top Layer w0.127: U6.D12@64.7,58.575 v1(65.25,59.125)
  Signal Layer 3 w0.102: v1(63.25,81.7) 69.796,81.7 v1(70.61,80.886)
  Bottom Layer w0.127: v1(63.25,81.7) 63.25,67.025 62.375,66.15 62.375,61.025 62.725,60.675 63.7,60.675 v1(65.25,59.125) ; v1(70.61,80.886) CN19.12@70.61,82.217
LCD_G5: CN19.14 U6.P4 | length 19.4
  Top Layer w0.1: 69.687,69.075 69.687,68.887 69.575,68.775 69.575,65.4 U6.P4@69.9,65.075
  Top Layer w0.127: 69.687,69.075 69.687,76.962 70,77.275 69.975,77.3 v1(69.975,80.675)
  Bottom Layer w0.127: v1(69.975,80.675) 70.25,80.4 71.271,80.4 71.88,81.009 CN19.14@71.88,82.217
LCD_G6: CN19.16 U6.D15 | length 46.8
  Top Layer w0.1: 59.175,59.15 59.675,59.15 60.125,58.7 62.625,58.7 U6.D15@62.75,58.575
  Top Layer w0.127: v1(58.013,59.15) 59.175,59.15
  Signal Layer 3 w0.102: v1(57.425,83.375) v1(67.4,83.375)
  Bottom Layer w0.127: v1(57.425,83.375) 57.425,66.65 57.65,66.425 58.35,66.425 58.575,66.2 58.575,64.225 58.013,63.662 v1(58.013,59.15) ; v1(67.4,83.375) 72.45,83.375 73.15,82.675 CN19.16@73.15,82.217
LCD_G7: CN19.18 U6.A9 | length 48.6
  Top Layer w0.1: v1(64.325,52.988) 64.325,53.35 66.65,55.675 U6.A9@66.65,56.625
  Signal Layer 3 w0.1: v1(64.325,52.988) 64.812,53.475 66.75,53.475 67.6,52.625
  Signal Layer 3 w0.102: 67.6,52.625 67.925,52.3 v1(76.475,52.3)
  Bottom Layer w0.127: CN19.18@74.42,82.217 74.42,81.055 75.175,80.3 75.9,80.3 76.325,79.875 76.325,76.875 76.475,76.725 v1(76.475,52.3)
LCD_HSYNC: CN19.26 U6.E14 | length 49.6
  Top Layer w0.1: v1(60.225,59.15) 60.475,58.9 63.075,58.9 U6.E14@63.4,59.225
  Signal Layer 3 w0.102: v1(60.895,82.1) 60.897,82.102 68.777,82.102 69.5,82.825 v1(69.5,84.752)
  Bottom Layer w0.127: v1(60.225,59.15) 60.225,60.958 60.627,61.36 60.627,68.198 59.633,69.192 59.633,76.557 60.895,77.82 v1(60.895,82.1) ; v1(69.5,84.752) 77.448,84.752 79.5,82.7 CN19.26@79.5,82.217
LCD_R0: CN19.3 U6.B4 | length 41.6
  Top Layer w0.1: v2(69.575,56.95) U6.B4@69.9,57.275
  Signal Layer 1 w0.1: v1(66.425,53.075) 66.775,53.075 68.375,54.675 68.375,55.75 v2(69.575,56.95)
  Signal Layer 3 w0.1: 65.975,52.625 v1(66.425,53.075)
  Signal Layer 3 w0.102: v1(60.975,77.2) v1(65.53,77.2) ; v1(64.325,52.25) 65.6,52.25 65.975,52.625
  Bottom Layer w0.127: v1(60.975,77.2) 60.975,75.675 60.375,75.075 60.375,69.225 61.054,68.546 61.054,61.183 60.694,60.823 60.694,58.405 62.075,57.025 62.075,54.92 61.987,54.832 61.987,54.138 63.875,52.25 v1(64.325,52.25) ; v1(65.53,77.2) CN19.3@65.53,78.531
LCD_R1: CN19.5 U6.R4 | length 16
  Top Layer w0.1: U6.R4@69.9,65.725 69.9,68.525 70.114,68.739 70.114,69.075
  Top Layer w0.127: 70.114,69.075 v1(70.114,76.775)
  Signal Layer 3 w0.102: v1(66.8,77.2) 67.225,76.775 v1(70.114,76.775)
  Bottom Layer w0.127: v1(66.8,77.2) CN19.5@66.8,78.531
LCD_R2: CN19.7 U6.N13 | length 24.9
  Top Layer w0.1: 60.06,69.075 60.06,68.24 61.309,66.991 61.309,66.609 62.558,65.359 62.827,65.359 63.075,65.111 63.075,64.9 63.225,64.75 63.725,64.75 U6.N13@64.05,64.425
  Top Layer w0.127: 60.06,69.075 v1(60.06,77.661)
  Signal Layer 3 w0.102: v1(60.06,77.661) 67.609,77.661 v1(68.07,77.2)
  Bottom Layer w0.127: v1(68.07,77.2) CN19.7@68.07,78.531
LCD_R3: CN19.9 U6.M14 | length 30
  Top Layer w0.1: 59.375,67.625 60.25,66.75 60.25,66.25 62.4,64.1 63.075,64.1 U6.M14@63.4,63.775
  Top Layer w0.127: v1(58.079,78.063) 58.079,68.65 59.03,67.699 59.301,67.699 59.375,67.625
  Signal Layer 3 w0.102: v1(58.079,78.063) 68.477,78.063 v1(69.34,77.2)
  Bottom Layer w0.127: v1(69.34,77.2) CN19.9@69.34,78.531
LCD_R4: CN19.11 U6.N14 | length 29.9
  Top Layer w0.1: 59.213,69.075 59.213,68.412 60.825,66.8 60.825,66.241 62.291,64.775 62.761,64.775 63.111,64.425 U6.N14@63.4,64.425
  Top Layer w0.127: v1(58.926,78.465) 59.213,78.178 59.213,69.075
  Signal Layer 3 w0.102: v1(58.926,78.465) 69.345,78.465 v1(70.61,77.2)
  Bottom Layer w0.127: v1(70.61,77.2) CN19.11@70.61,78.531
LCD_R5: CN19.13 U6.M13 | length 34.9
  Top Layer w0.127: v1(57.925,78.875) 57.652,78.602 57.652,68.452 58.906,67.198 59.027,67.198 v1(59.35,66.875) ; v2(63.725,64.1) U6.M13@64.05,63.775
  Signal Layer 1 w0.1: v1(59.35,66.875) 60.95,66.875 v2(63.725,64.1)
  Signal Layer 3 w0.102: v1(57.925,78.875) 70.205,78.875 v1(71.88,77.2)
  Bottom Layer w0.127: v1(71.88,77.2) CN19.13@71.88,78.531
LCD_R6: CN19.15 U6.C4 | length 45.2
  Top Layer w0.127: U6.C4@69.9,57.925 v2(70.225,57.6)
  Signal Layer 1 w0.1: v2(70.225,57.6) 70.45,57.375 70.45,56.35 70.055,55.955 70.055,54.795 70.375,54.475 70.375,53.275 70.7,52.95 70.7,50.488 71.313,49.875 v1(73.6,49.875)
  Signal Layer 3 w0.102: v1(73.2,75.001) v1(76.025,75.001) ; v1(73.6,49.875) v1(76.025,49.875)
  Bottom Layer w0.127: CN19.15@73.15,78.531 73.2,78.481 v1(73.2,75.001) ; v1(76.025,49.875) v1(76.025,75.001)
LCD_R7: CN19.17 U6.P14 | length 32
  Top Layer w0.1: 60.487,69.075 60.487,68.176 61.6,67.063 61.6,66.6 62.15,66.05 62.875,66.05 63.075,65.85 63.075,65.4 U6.P14@63.4,65.075
  Top Layer w0.127: 60.487,69.075 v1(60.487,79.286)
  Signal Layer 3 w0.102: v1(60.487,79.286) 72.334,79.286 v1(74.42,77.2)
  Bottom Layer w0.127: v1(74.42,77.2) CN19.17@74.42,78.531
LCD_RST: SB43.2 U6.P15 | length 54.4
  Top Layer w0.1: 59.636,69.075 59.636,68.364 61.054,66.946 61.054,66.471 62.45,65.075 U6.P15@62.75,65.075
  Top Layer w0.12: v1(57.925,84.425) 57.925,83.95 59.636,82.239 59.636,69.075
  Signal Layer 3 w0.12: v1(57.925,84.425) 58.775,85.275 70.225,85.275 70.45,85.05 87.975,85.05 v1(88.925,86)
  Bottom Layer w0.12: SB43.2@87.9,86 v1(88.925,86)
LCD_VSYNC: CN19.28 U6.P5 | length 30.3
  Top Layer w0.1: 68.833,69.092 68.833,69.025 68.95,68.908 68.95,65.375 U6.P5@69.25,65.075
  Top Layer w0.127: 68.833,69.092 v1(68.833,80.374)
  Signal Layer 3 w0.102: v1@68.833,80.383 69.08,80.136 77.358,80.136 v1(80.77,83.548)
  Bottom Layer w0.127: CN19.28@80.77,82.217 v1(80.77,83.548)
LED_G_A: CN3.12 R70.1 U9.3 | length 36
  Top Layer w0.12: U9.3@118.7,49.55 121.025,49.55 R70.1@121.1,49.475
  Signal Layer 3 w0.127: v1(119.425,49.55) v1(122.9,49.55)
  Bottom Layer w0.127: v1(122.9,49.55) 122.2,50.25 122.2,64.739 123.425,65.964 123.425,73.53 124.36,74.465 CN3.12@124.36,78.505
LED_G_K: CN3.11 R6.2 | length 6.6
  Top Layer w0.12: CN3.11@122.07,78.505 122.95,77.625 125.85,77.625 126.708,78.483 R6.2@127.932,78.483
LED_STLK: R130.2 R131.2 U13.D15 | length 33.5
  Top Layer w0.12: v1(111.975,9.275) 119.326,9.275 R130.2@119.336,9.264 R131.2@120.836,9.264 ; v1(112.308,32.902) U13.D15@112.633,32.577
  Bottom Layer w0.12: v1(111.975,9.275) 111.975,22.832 112.063,22.92 112.063,25.507 112.776,26.219 112.776,31.141 112.308,31.608 v1(112.308,32.902)
LED_Y_A: CN3.10 R71.2 U9.2 | length 35.3
  Top Layer w0.12: U9.2@118.7,49.05 v1(119.8,49.05) 120.45,48.4 R71.2@121.1,48.4
  Bottom Layer w0.127: CN3.10@112.53,78.505 112.53,72.995 118.425,67.1 118.425,63.2 120.034,61.591 120.034,49.283 v1(119.8,49.05)
LED_Y_K: CN3.9 R13.2 | length 3.7
  Top Layer w0.12: CN3.9@110.24,78.505 110.24,76.91 110.6,76.55 R13.2@110.6,75
MCO: C72.2 R88.2 TP3.1 | length 5.7
  Top Layer w0.12: TP3.1@112.261,41.514 112.261,36.864 C72.2@112.236,36.839 R88.2@113.236,36.839
MEMS_LED: CN20.12 U6.G12 | length 81.6
  Top Layer w0.127: U6.G12@64.7,60.525 v1(65.3,60.525)
  Signal Layer 3 w0.09: 7.06,40.767 8.45,40.767
  Signal Layer 3 w0.12: 8.45,40.767 v1(16.742,40.767) ; v1(18.325,61.975) 19.05,61.25 20.325,61.25 20.7,61.625 30.05,61.625 30.639,61.036 45.795,61.036 46.395,60.436 52.361,60.436 53.2,61.275 54,61.275 54.375,60.9 60.45,60.9 60.825,60.525 v1(65.3,60.525)
  Signal Layer 3 w0.127: CN20.12@6.425,41.402 7.06,40.767
  Bottom Layer w0.12: v1(16.742,40.767) 18.325,42.35 18.325,47.6
  Bottom Layer w0.127: 18.325,47.6 v1(18.325,61.975)
MIC_CLK: SB38.1 SB40.1 U33.3 | length 4.6
  Bottom Layer w0.12: U33.3@39.074,4.073 39.349,4.073 40.299,3.123 SB38.1@41.799,3.123 SB40.1@41.799,1.673
MIC_DATA: SB28.1 SB39.1 U33.4 | length 34.7
  Top Layer w0.12: v1(34.1,24.625) SB28.1@34.1,26.775
  Bottom Layer w0.12: v1(34.1,24.625) 34.1,10.875 30.6,7.375 30.6,2.95 31.875,1.675 SB39.1@36.4,1.675 36.4,3.024 37.449,4.073 U33.4@37.724,4.073
NetB2_3: B2.3 B2.4 C138.2 R141.1 R142.2 U32.1 | length 15
  Bottom Layer w0.12: C138.2@147.775,55.4 R141.1@147.775,54.4 R142.2@147.775,53.35 147.775,52.175 U32.1@147.95,52 148,51.95 B2.3@149.925,51.95 B2.4@149.925,61.45
NetC1_2: C1.2 C2.2 C7.2 C8.2 C9.1 D1.2 L1.2 R11.2 R17.2 | length 70.3
  Top Layer w0.6: C7.2@98.736,83.589 99.061,83.589 99.661,82.989 C1.2@101.461,82.989 C2.2@104.586,82.989 104.751,82.825 105.425,82.825 105.375,82.775 105.525,82.625 105.525,81.85 v1(105.725,81.65) ; L1.2@102.656,71.614 102.656,72.281 102.864,72.489 R17.2@104.761,72.489 105.375,73.103 v1(105.375,74.475) ; v1(127.589,82.889) C9.1@128.961,82.889 129.086,83.014 C8.2@129.086,84.214 131.551,84.214 D1.2@131.561,84.204 137.221,84.204 139.461,81.964 R11.2@139.461,76.914
  Signal Layer 3 w0.6: v1(105.375,74.475) 108.15,77.25 109.225,77.25 111.725,74.75 123.95,74.75 127.589,78.389 v1(127.589,82.889)
  Bottom Layer w0.6: v1(105.375,74.475) 105.725,74.825 v1(105.725,81.65)
NetC9_2: C9.2 C13.1 C52.2 C59.2 C60.1 D1.1 D7.1 R10.2 R74.1 R75.1 U8.8 U8.EP | length 76.4
  Top Layer w0.381: v1(101.711,43.414) C59.2@101.711,44.764 ; v1(103.325,43.414) 103.336,43.425 R74.1@103.336,44.264 ; v1(104.961,43.414) C60.1@104.961,44.764 ; v1(106.361,43.414) R75.1@106.361,44.764
  Top Layer w0.4: U8.8@104.851,48.396 106.107,48.396 C52.2@106.157,48.446
  Top Layer w0.6: C52.2@106.157,48.446 v1(107.05,48.446) 107.321,48.446 108.339,49.464 D7.1@108.836,49.464 ; v1(129.897,79.889) C13.1@129.111,79.889 129.111,81.039 C9.2@128.961,81.189 130.336,81.189 131.351,80.174 D1.1@131.561,80.174 133.326,80.174 134.361,79.139 R10.2@134.361,76.914
  Signal Layer 3 w0.6: v1(107.05,48.446) 109.354,50.75 114.45,50.75 115.25,51.55 131.425,51.55 v1(132.35,52.475)
  Bottom Layer w0.6: v1(129.897,79.889) 129.897,68.478 133.65,64.725 133.65,53.775 v1(132.35,52.475)
  other v1: 101.076,49.696 102.576,49.696 104.076,49.696 104.076,51.15 102.576,51.196 101.076,51.225 101.076,52.696 102.6,52.696 104.076,52.696
NetC10_2: C10.2 C15.1 C16.1 C17.1 C20.1 | length 32
  Top Layer w0.12: v1(132.411,76) C15.1@132.411,76.964
  Top Layer w0.6: C10.2@107.286,78.214 107.036,78.214 106.336,77.514 C16.1@106.336,76.789 C17.1@107.711,76.789 108.136,76.789 v1(108.45,76.475) ; C20.1@132.411,75.089 v1(132.411,76)
  Signal Layer 3 w0.6: v1(108.45,76.475) 108.925,76.475 111.5,73.9 124.275,73.9 124.6,74.225 130.636,74.225 v1(132.411,76)
NetC11_2: C11.2 C12.2 D2.2 R2.1
NetC12_1: C12.1 R7.2 | length 1.6
  Top Layer w0.6: R7.2@75.436,77.964 C12.1@75.436,79.589
NetC14_1: C14.1 R5.1 | length 2.2
  Top Layer w0.6: C14.1@101.911,77.214 101.911,78.114 102.686,78.889 R5.1@102.686,79.114
NetC15_2: C15.2 R9.1 | length 1.4
  Top Layer w0.12: R9.1@129.638,76.959 R9.1@129.643,76.964
  Top Layer w0.6: R9.1@129.643,76.964 C15.2@131.011,76.964
NetC16_2: C16.2 R14.1 | length 1.4
  Top Layer w0.6: C16.2@106.336,75.389 106.4,75.326 106.4,74.451 R14.1@106.711,74.139
NetC17_2: C17.2 R15.1 | length 1.8
  Top Layer w0.6: C17.2@107.711,75.389 108.072,75.389 108.586,74.875 R15.1@108.586,74.139
NetC19_1: C19.1 D4.4 D5.4 R10.1 | length 15.5
  Top Layer w0.6: D4.4@125.336,72.354 126.857,73.875 132.841,73.875 D5.4@134.361,72.354 134.379,72.354 136.086,74.061 C19.1@136.086,75.164 R10.1@134.361,75.164
NetC19_2: C19.2 D4.3 D5.3 R11.1 | length 16.1
  Top Layer w0.6: D4.3@130.436,72.354 132.101,70.689 137.796,70.689 D5.3@139.461,72.354 139.371,72.354 137.486,74.239 C19.2@137.486,75.164 R11.1@139.461,75.164
NetC20_2: C20.2 R12.1 | length 1.4
  Top Layer w0.6: R12.1@129.636,75.089 C20.2@131.011,75.089
NetC21_2: C21.2 U1.4 | length 2
  Top Layer w0.45: C21.2@78.211,73.039 78.411,73.039 78.9,72.551 U1.4@78.9,71.4
NetC22_2: C22.2 SB3.1 | length 1.4
  Top Layer w0.35: SB3.1@64.225,69.725 C22.2@64.225,71.175
NetC25_1: C25.1 R18.1 U2.1 | length 3.7
  Top Layer w0.6: R18.1@90.411,71.964 90.411,71.436 90.161,71.186 C25.1@90.161,70.339 90.811,70.339 91.626,69.524 U2.1@91.786,69.524
NetC27_1: C27.1 C29.1 C31.2 R26.1 U3.3 | length 6.1
  Top Layer w0.6: U3.3@85.711,66.864 86.386,67.539 C27.1@87.461,67.539 C29.1@88.761,67.539 C31.2@88.761,66.164 R26.1@88.761,64.764
NetC27_2: C27.2 R19.1 R20.1 R21.2 R23.1 U3.4 | length 8
  Top Layer w0.6: R19.1@85.411,72.164 R21.2@85.411,70.739 R21.2@85.601,70.55 ; R20.1@87.111,70.989 86.672,70.55 R21.2@85.601,70.55 ; R23.1@88.761,68.939 C27.2@87.461,68.939 85.836,68.939 U3.4@85.711,69.064 85.711,70.439 R21.2@85.601,70.55
NetC28_2: C28.2 R22.1 | length 1.4
  Top Layer w0.12: C28.2@101.286,67.839 R22.1@101.286,69.214
NetC29_2: C29.2 R23.2 | length 1.4
  Top Layer w0.6: C29.2@90.161,67.539 R23.2@90.161,68.939
NetC31_1: C31.1 R26.2 U2.2 | length 4.9
  Top Layer w0.6: R26.2@90.161,64.764 C31.1@90.161,66.164 91.364,66.164 91.786,66.586 U2.2@91.786,68.254
NetC34_1: C34.1 C36.1 C55.1 C56.2 C61.1 C62.2 L4.1 R76.2 R77.2 R78.2 R79.2 SB9.1 U9.1 U9.19 | length 32.7
  Top Layer w0.2: v1(113.75,46.375) 113.75,45.65 C61.1@114.125,45.275 ; C61.1@114.125,45.325 114.275,45.475 114.275,45.95 115.5,47.175 U9.19@115.5,47.85 ; v1(115.125,43.85) R76.2@115.125,44.375 ; v1(116.2,43.85) R77.2@116.2,44.375 ; v1(117.275,43.85) R78.2@117.275,44.375 ; v1(118.35,43.85) R79.2@118.35,44.375 ; U9.1@118.7,48.55 119.375,48.55 120.5,47.425 C55.1@121.1,47.425 121,47.325 121,46.425 C56.2@120.85,46.275
  Top Layer w0.35: v1(111.35,46.8) 111.875,46.275 L4.1@111.875,44.95 C62.2@111.875,43.725 v1(112.45,43.725)
  Top Layer w0.381: v1(115.3,59.325) 115.85,59.875 C36.1@115.85,60.25 C34.1@115.85,61.3 117.45,61.3 SB9.1@117.65,61.1
  Signal Layer 2 w0.6: v1(111.35,46.8) 112.575,48.025 112.575,56.6 v1(115.3,59.325)
  other v1: 120.025,47.9
NetC35_2: C35.2 L2.2 U6.G1 | length 5.3
  Top Layer w0.25: U6.G1@71.85,60.525 72.475,60.525
  Top Layer w0.35: 72.475,60.525 74.425,60.525 74.575,60.375 75.575,60.375 C35.2@75.6,60.35 76.025,59.925 76.625,59.925 L2.2@76.825,59.725
NetC38_2: C38.2 SB13.1 | length 1.7
  Top Layer w0.35: SB13.1@79.225,58.225 C38.2@80.875,58.225
NetC39_2: C39.2 R47.1 U8.13 | length 3.7
  Top Layer w0.4: C39.2@100.461,56.139 R47.1@101.811,56.139 102.251,55.7 U8.13@102.251,53.996
NetC40_2: C40.2 R8.1 U8.12 | length 29.1
  Top Layer w0.4: U8.12@102.901,53.996 v1(102.901,55.376) 103.211,55.686 C40.2@103.211,56.139
  Top Layer w0.508: R8.1@103.261,77.189 103.261,77.501 v1(103.6,77.839)
  Bottom Layer w0.508: v1(102.901,55.376) 102.425,55.852 102.425,61.2 100.264,63.361 100.264,65.364 100.75,65.85 102.116,65.85 103.95,67.684 103.95,69.7 103.6,70.05 v1(103.6,77.839)
NetC41_2: C41.2 C42.2 D3.2 R8.2 U8.11 | length 29.7
  Top Layer w0.4: U8.11@103.551,53.996 103.551,55.151 104.539,56.139 C41.2@104.586,56.139 C42.2@105.961,56.139 v1(106.889,56.139)
  Top Layer w0.55: D3.2@104.436,78.844 104.436,78.175 104.661,77.95 R8.2@104.661,77.189
  Top Layer w0.6: v1(104.661,76.239) R8.2@104.661,77.189
  Bottom Layer w0.6: v1(104.661,76.239) 104.475,76.052 104.475,73.425 107.975,69.925 107.975,57.225 v1(106.889,56.139)
NetC43_2: C43.2 L3.2 U6.F1 | length 7.5
  Top Layer w0.25: U6.F1@71.85,59.875 71.85,59.889 71.861,59.9 73.125,59.9
  Top Layer w0.35: 73.125,59.9 74.875,58.15 74.875,57.475 75.6,56.75 L3.2@76.075,56.75 C43.2@77.625,56.75
NetC44_2: C44.2 SB16.1 | length 1.1
  Top Layer w0.35: C44.2@55.95,55.475 57.05,55.475
NetC45_2: C45.2 R54.2 X2.1 | length 3.1
  Top Layer w0.12: R54.2@77.325,54.975 77.325,55.2 77.775,55.65 C45.2@78.275,55.65 79.775,55.65 X2.1@79.925,55.5
NetC48_2: C48.2 R62.2 X2.2 | length 3.1
  Top Layer w0.12: R62.2@77.325,53.525 77.325,53.3 77.775,52.85 C48.2@78.275,52.85 79.775,52.85 X2.2@79.925,53
NetC50_2: C50.2 C51.2 U9.6 | length 3.9
  Top Layer w0.12: U9.6@118.7,51.05 119.6,51.05 120.1,51.55 C51.2@121.1,51.55 121.1,52.45 C50.2@120.85,52.7
NetC53_2: C53.2 SB19.1 | length 1.4
  Top Layer w0.35: C53.2@67.65,49.7 SB19.1@67.65,51.15
NetC57_1: C57.1 U8.2 | length 3.7
  Top Layer w0.4: C57.1@98.961,46.164 98.961,46.686 99.45,47.175 100.6,47.175 100.951,47.526 U8.2@100.951,48.396
NetC58_1: C58.1 U8.3 | length 2.8
  Top Layer w0.4: C58.1@100.336,46.164 100.414,46.164 101.6,47.35 U8.3@101.6,48.396
NetC59_1: C59.1 R17.1 U8.4 | length 28.7
  Top Layer w0.4: C59.1@101.711,46.164 102.251,46.704 v1(102.251,47.025) U8.4@102.251,48.396
  Top Layer w0.508: v1(104.761,69.939) R17.1@104.761,70.739
  Bottom Layer w0.508: v1(102.251,47.025) 103.18,47.025 105.075,48.92 105.075,52.35 105.9,53.175 105.9,68.8 v1(104.761,69.939)
NetC60_2: C60.2 U8.6 | length 2.9
  Top Layer w0.4: U8.6@103.551,48.396 103.551,47.374 104.761,46.164 C60.2@104.961,46.164
NetC64_1: C64.1 U12.G8 | length 7.9
  Top Layer w0.09: 35.9,34.375 36.475,34.375 U12.G8@36.725,34.125
  Top Layer w0.1: 33.2,36.8 34.3,36.8 35.425,35.675 35.425,34.75 35.8,34.375 35.9,34.375
  Top Layer w0.12: 33.2,36.8 33.025,36.8 32.85,36.975 32.85,38.025 33.65,38.825 C64.1@33.75,38.825
NetC64_2: C64.2 U12.H8 | length 4.2
  Top Layer w0.1: C64.2@33.75,37.425 33.875,37.425 34.3,37 34.45,37 35.725,35.725 35.725,35.625 U12.H8@36.725,34.625
NetC65_2: C65.2 U12.G7 | length 4.2
  Top Layer w0.09: 36.975,34.95 36.975,34.375 U12.G7@37.225,34.125
  Top Layer w0.1: C65.2@35.125,37.425 35.125,36.9 36.975,35.05 36.975,34.95
NetC66_2: C66.2 U12.H7 | length 3.1
  Top Layer w0.1: C66.2@36.5,37.425 36.5,36.15 37.225,35.425 U12.H7@37.225,34.625
NetC67_2: C67.2 U13.M10 | length 7
  Top Layer w0.12: U13.M10@117.833,29.327 118.158,29.652 118.158,33.177 120.131,35.15 C67.2@120.381,35.15
NetC68_1: C68.1 CN10.4 U12.G6 U19.1 | length 43.3
  Top Layer w0.09: 37.475,34.95 37.475,34.375 U12.G6@37.725,34.125
  Top Layer w0.1: 37.475,34.95 v1(37.475,36.225) 38.125,36.875 38.625,36.875 C68.1@39.1,37.35
  Top Layer w0.12: CN10.4@28.775,5.8 28.775,20.475 30.35,22.05 U19.1@37.5,22.05
  Bottom Layer w0.1: 35.85,27.5 35.85,34.6 v1(37.475,36.225)
  Bottom Layer w0.12: v1(35.85,22.05) 35.85,25.047 35.93,25.127 35.93,25.543 35.85,25.623 35.85,27.5
NetC68_2: C68.2 R84.2 | length 1.4
  Top Layer w0.12: R84.2@37.9,38.825 38.125,38.6 38.75,38.6 C68.2@39.1,38.25
NetC69_1: C69.1 CN10.6 U12.H6 U19.3 | length 30.3
  Top Layer w0.1: U12.H6@37.725,34.625 37.725,35.892 38.433,36.6 v1(39.275,36.6) C69.1@40.025,37.35
  Top Layer w0.12: CN10.6@35.675,13.2 35.675,19.525 v1(36.3,20.15) U19.3@37.5,20.15
  Bottom Layer w0.1: 36.3,27.5 36.3,33.625 v1(39.275,36.6)
  Bottom Layer w0.12: v1(36.3,20.15) 36.3,27.5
